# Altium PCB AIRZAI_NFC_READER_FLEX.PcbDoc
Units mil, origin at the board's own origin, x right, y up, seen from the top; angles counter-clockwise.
Board outline 2897.24 x 5858.66 mil, 2 copper layers (Top Layer, Bottom Layer); 43 components, 43 nets, 191 pads, 93 vias.
Unrouted connection lines stored in the file: 129.
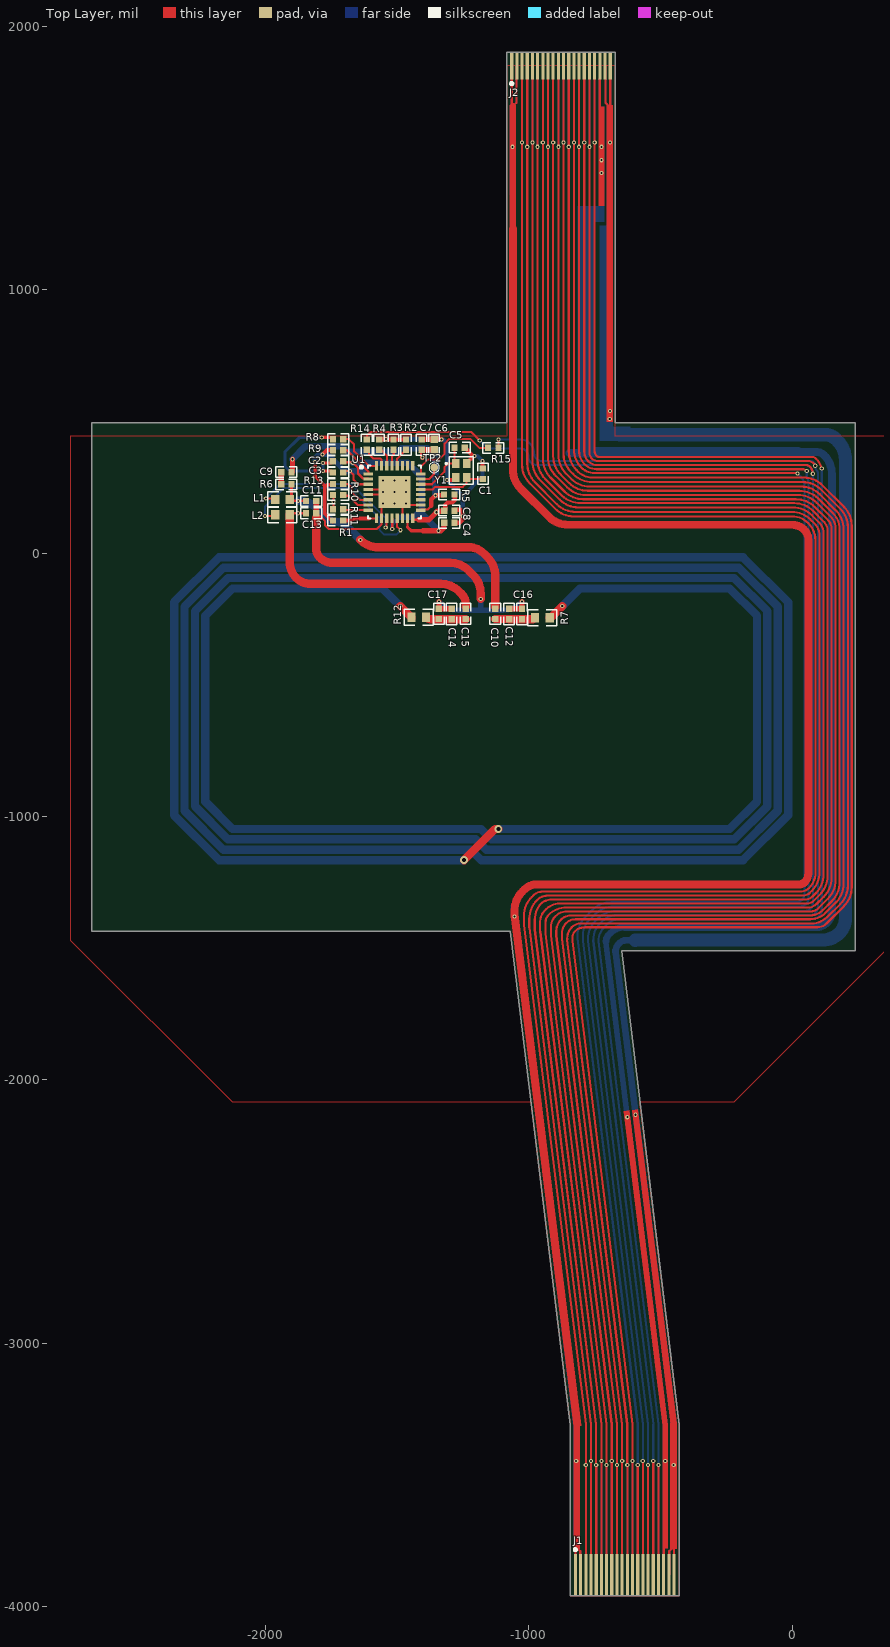
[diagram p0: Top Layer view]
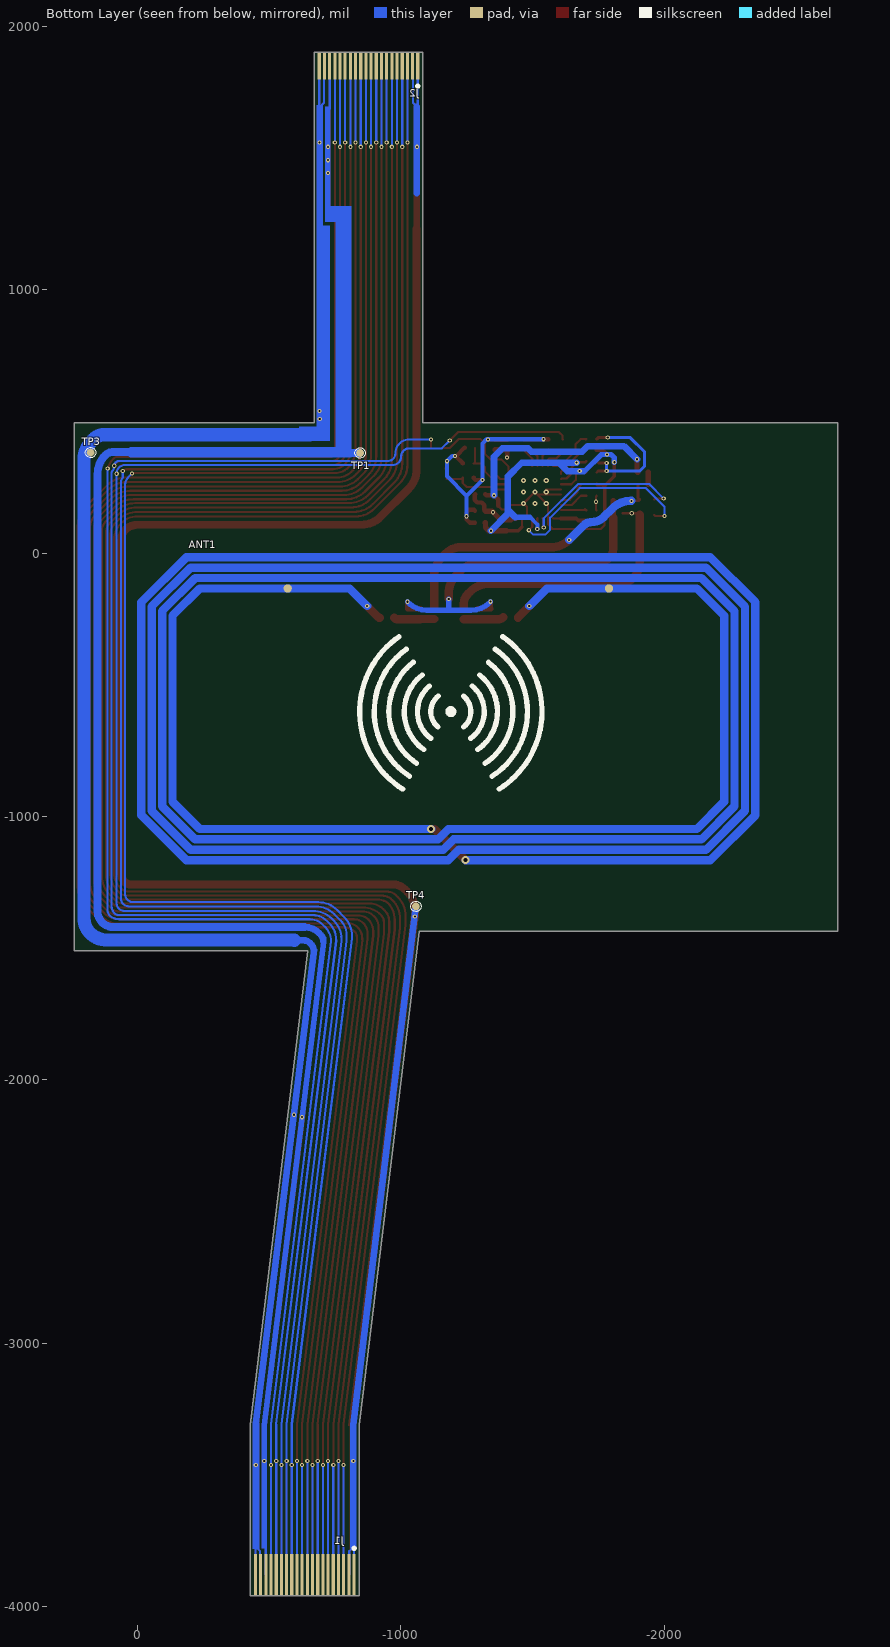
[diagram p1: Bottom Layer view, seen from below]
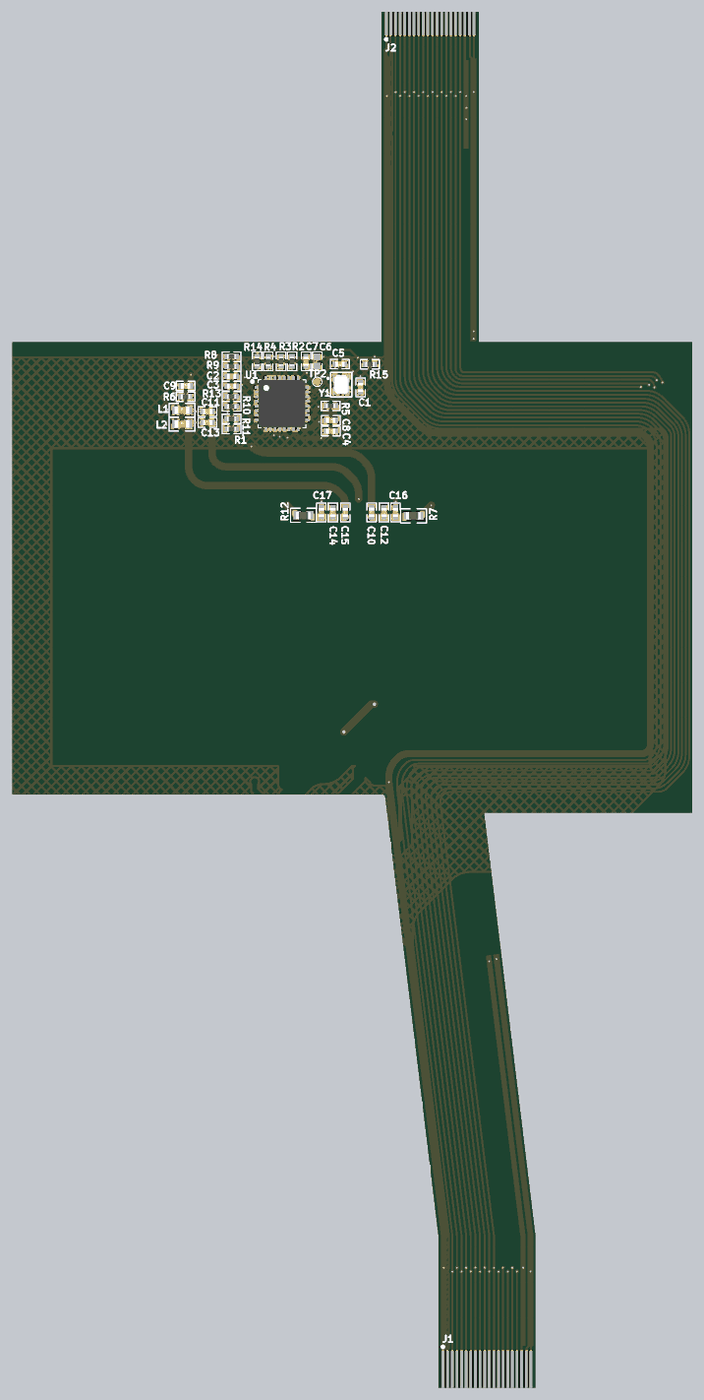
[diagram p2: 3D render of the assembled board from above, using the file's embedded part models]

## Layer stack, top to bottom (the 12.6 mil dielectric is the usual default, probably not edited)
Top Solder: solder mask 0.4, Solder Resist, Dk 3.5
Top Layer: signal copper 1.4
Dielectric 1: dielectric 12.6, FR-4, Dk 4.8
Bottom Layer: signal copper 1.4
Bottom Solder: solder mask 0.4, Solder Resist, Dk 3.5

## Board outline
-2658.83,-1434.65 -2658.83,494.46 -1084.81,494.46 -1084.81,1901.16 -671.43,1901.16 -671.43,494.46 238.42,494.46 238.42,-1510 -648.12,-1510 -648.12,-1510.01 -429.3,-3309.99 -429.3,-3957.5 -842.69,-3957.5 -842.69,-3309.99 -1070.67,-1434.65 -1070.68,-1434.65

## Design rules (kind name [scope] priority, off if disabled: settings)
Clearance Clearance_polygon_5V [OnLayer('Keep-Out Layer') vs (InNet('+5V') AND InPolygon)] p1: gap=10 ignorepadtopadclearanceinfootprint=FALSE
Clearance Clearance_POLYGON_KEEPOUT [(OnLayer('Keep-Out Layer')) vs (InNet('GND') AND InPolygon)] p2: gap=10 ignorepadtopadclearanceinfootprint=FALSE
Clearance [All] p3: gap=6 ignorepadtopadclearanceinfootprint=FALSE
MinimumSolderMaskSliver [All] p1: minsoldermaskwidth=1
PolygonConnect [All] p1: connectstyle=Direct reliefconductorwidth=10 reliefentries=4 polygonreliefangle="90 Angle" airgapwidth=10
RoomDefinition AIRZAI_NFC_READER_FLEX [InComponentClass('AIRZAI_NFC_READER_FLEX')] p1: confinementstyle=ConfineIn formatcopy=TRUE lockcomponents=FALSE outline -17880.56,-16733.69 13049.31,-16733.69 13049.31,5823.5 -17880.56,5823.5
RoutingVias [All] p1: holewidth=28 width=50 viastyle="Through Hole" minholewidth=8 minwidth=16 maxholewidth=28 maxwidth=50
SilkToSilkClearance [All] p1: silktosilkclearance=1
SilkToSolderMaskClearance [IsPad] p1: minsilkscreentomaskgap=2 clearancetoexposedcopper=TRUE
SolderMaskExpansion [All] p1: expansion=4
UnRoutedNet [All] p1: checkbadconnections=TRUE
Width [All] p1: maxlimit=100 minlimit=6 preferedwidth=10
26 further rules are at their usual default settings.

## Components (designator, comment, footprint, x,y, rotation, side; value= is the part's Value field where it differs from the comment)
ANT1 "NFC_ANT" ANTENNA-NFC-60MMX30MM -1181.1,-590.55 r180 bottom locked
C1 "12pF" 0402CAP -1174.8,301.42 r270 top
C2 "0.1µF" 0402CAP -1724.45,348.95 r180 top
C3 "0.1µF" 0402CAP -1724.45,306.27 r180 top
C4 "0.1µF" 0402CAP -1301.78,115.39 r0 top
C5 "12pF" 0402CAP -1262.89,400.56 r180 top
C6 "1uF" CAPC0402(1005)60_M -1359.58,412.18 r270 top
C7 "0.1µF" 0402CAP -1406.8,412.31 r90 top
C8 "0.1µF" 0402CAP -1301.78,161.39 r0 top
C9 "1nF" 0402CAP -1920.38,307.56 r0 top
C10 "18pF" 0402CAP -1127.69,-230.53 r90 top
C11 "220pF" 0402CAP -1826.95,198.56 r180 top
C12 "47pF" 0402CAP -1074.78,-230.87 r270 top
C13 "220pF" 0402CAP -1826.95,151.56 r0 top
C14 "47pF" 0402CAP -1293.1,-230.88 r90 top
C15 "18pF" 0402CAP -1239.99,-230.69 r90 top
C16 "DNP" 0402CAP -1025.76,-230.87 r270 top
C17 "DNP" 0402CAP -1341.78,-230.69 r90 top
J1 "FFC Cable" FFC_PADS_MBD -645.83,-3878.76 r180 top locked
J2 "FFC Cable" FFC_PADS_LID -887.96,1849.98 r180 top locked
L1 "560nH" 0603CAP -1935.38,203.56 r0 top
L2 "560mH" 0603CAP -1935.38,145.56 r0 top
R1 "0R" 0402 -1724.42,124.11 r180 top
R2 "10K" 0402 -1466.8,412.31 r270 top
R3 "10K" 0402 -1513.8,412.31 r270 top
R4 "10K" 0402 -1568.42,412.11 r270 top
R5 "1K" 0402 -1302.26,222.84 r180 top
R6 "2.7K" 0402 -1920.7,261.56 r180 top
R7 "3.3" 0603 -948.78,-245.53 r180 top
R8 "10K" 0402 -1724.42,432.89 r180 top
R9 "10K" 0402 -1724.42,391.11 r180 top
R10 "0R" 0402 -1724.26,221.11 r180 top
R11 "0R" 0402 -1724.42,167.11 r180 top
R12 "3.3" 0603 -1417.78,-243.31 r0 top
R13 "10K" 0402 -1724.42,263.11 r180 top
R14 "0R" 0402 -1615.42,412.37 r90 top
R15 "0R" 0402 -1135,399.88 r0 top
TP1 "WIREPT" TP_0.9MM -846,380.56 r90 bottom
TP2 "WIREPT" TP_0.9MM -1359.42,325.11 r270 top
TP3 "WIREPT" TP_0.9MM 177,382 r90 bottom
TP4 "WIREPT" TP_0.9MM -1058,-1341 r90 bottom
U1 "MFRC52202HN1,115" VFQFN-32-MFRC52202HN1,157 -1509.78,232.11 r0 top
Y1 "27.12MHz" XTAL_2016 -1256.78,313.42 r270 top

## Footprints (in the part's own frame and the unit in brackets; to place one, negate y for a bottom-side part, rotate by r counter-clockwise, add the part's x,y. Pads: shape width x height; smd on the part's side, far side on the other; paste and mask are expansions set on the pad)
0402 [mm] "Chip Resistor, Body 1.1x0.5mm, IPC High Density"
  rect 0.6x0.6 smd: 1(-0.5,0) 2(0.5,0)
  silkscreen extent -1.02,-0.51 1.02,0.51, body extent -0.5,-0.25 0.5,0.25, height 0.27
0402CAP [mm] "Chip Capacitor, Body 1.1x0.5mm, IPC High Density"
  rect 0.6x0.6 smd: 1(-0.5,0) 2(0.5,0)
  silkscreen extent -1.02,-0.51 1.02,0.51, body extent -0.5,-0.3 0.5,0.3, height 0.19
0603 [mm] "Chip Resistor, Body 1.6x0.8mm, IPC High Density"
  rect 0.8x0.9 smd: 1(-0.7,0) 2(0.7,0)
  silkscreen extent -1.4,-0.76 1.4,0.76, body extent -0.8,-0.41 0.8,0.4, height 0.37
0603CAP [mm] "Chip Capacitor, Body 1.6x0.8mm, IPC High Density"
  rect 0.8x0.9 smd: 1(-0.7,0) 2(0.7,0)
  silkscreen extent -1.4,-0.76 1.4,0.76, body extent -0.8,-0.4 0.8,0.4, height 0.29
ANTENNA-NFC-60MMX30MM [mm] "ANTENNA-ID2+10P-01"
  round 0.8 smd paste-0.8: 1(-15.494,11.6) 2(15.494,11.6)
  Top Layer lines w0.8: 15.494,11.6 23.97,11.6 26.6,8.97 26.6,-8.97 23.97,-11.6 0,-11.6 -1,-12.6 -24.404,-12.6 -27.6,-9.404 -27.6,9.404 -24.404,12.6 24.404,12.6 27.6,9.404 27.6,-9.404 24.404,-12.6 0.508,-12.6 -0.492,-13.6 -24.838,-13.6 -28.6,-9.838 -28.6,9.838 -24.838,13.6 24.838,13.6 28.6,9.838 28.6,-9.838 24.838,-13.6 1,-13.6 0,-14.6 -25.272,-14.6 -29.6,-10.272 -29.6,10.272 -25.272,14.6 25.272,14.6 29.6,10.272 29.6,-10.272 25.272,-14.6 1.651,-14.6 ; -1.651,-11.6 -23.97,-11.6 -26.6,-8.97 -26.6,8.97 -23.97,11.6 -15.494,11.6
  Bottom Layer lines w0.8: 1.651,-14.6 -1.349,-11.6 -1.651,-11.6
CAPC0402(1005)60_M [mm] "Chip Capacitor, Body 1.0x0.5mm, Height 0.6mm, IPC Low Density"
  rect 0.72x0.72 smd: 1(-0.5,0) 2(0.5,0)
  silkscreen extent -1.02,-0.51 1.02,0.51, body extent -0.55,-0.3 0.55,0.3, height 0.6
FFC_PADS_LID [mm] "(0.50mm"
  rect 0.3x2.6 smd: 1(4.5,0) 2(4,0) 3(3.5,0) 4(3,0) 5(2.5,0) 6(2,0) 7(1.5,0) 8(1,0) 9(0.5,0) 10(0,0) 11(-0.5,0) 12(-1,0) 13(-1.5,0) 14(-2,0) 15(-2.5,0) 16(-3,0) 17(-3.5,0) 18(-4,0) 19(-4.5,0) 20(-5,0)
  rect 0.3x2.6 smd far side: 1(4.5,0) 2(4,0) 3(3.5,0) 4(3,0) 5(2.5,0) 6(2,0) 7(1.5,0) 8(1,0) 9(0.5,0) 10(0,0) 11(-0.5,0) 12(-1,0) 13(-1.5,0) 14(-2,0) 15(-2.5,0) 16(-3,0) 17(-3.5,0) 18(-4,0) 19(-4.5,0) 20(-5,0)
  silkscreen extent 4.37,1.58 4.62,1.83
FFC_PADS_MBD [mm] "(0.50mm"
  rect 0.3x4 smd: 1(4.5,0) 2(4,0) 3(3.5,0) 4(3,0) 5(2.5,0) 6(2,0) 7(1.5,0) 8(1,0) 9(0.5,0) 10(0,0) 11(-0.5,0) 12(-1,0) 13(-1.5,0) 14(-2,0) 15(-2.5,0) 16(-3,0) 17(-3.5,0) 18(-4,0) 19(-4.5,0) 20(-5,0)
  rect 0.3x4 smd far side: 1(4.5,0) 2(4,0) 3(3.5,0) 4(3,0) 5(2.5,0) 6(2,0) 7(1.5,0) 8(1,0) 9(0.5,0) 10(0,0) 11(-0.5,0) 12(-1,0) 13(-1.5,0) 14(-2,0) 15(-2.5,0) 16(-3,0) 17(-3.5,0) 18(-4,0) 19(-4.5,0) 20(-5,0)
  silkscreen extent 4.39,-2.56 4.64,-2.31
TP_0.9MM [mm] "0.9MM DIA TESTPOINT"
  round 0.75 smd paste-5 mask+0.05: 1(0,0)
  silkscreen extent -0.5,-0.5 0.5,0.5
VFQFN-32-MFRC52202HN1,157 [mm]
  rect 0.9x0.31 smd: 1(-2.529,1.75) 2(-2.529,1.25) 3(-2.529,0.75) 4(-2.529,0.25) 5(-2.529,-0.25) 6(-2.529,-0.75) 7(-2.529,-1.25) 8(-2.529,-1.75) 17(2.529,-1.75) 18(2.529,-1.25) 19(2.529,-0.75) 20(2.529,-0.25) 21(2.529,0.25) 22(2.529,0.75) 23(2.529,1.25) 24(2.529,1.75)
  rect 0.31x0.9 smd: 9(-1.75,-2.529) 10(-1.25,-2.529) 11(-0.75,-2.529) 12(-0.25,-2.529) 13(0.25,-2.529) 14(0.75,-2.529) 15(1.25,-2.529) 16(1.75,-2.529) 25(1.75,2.529) 26(1.25,2.529) 27(0.75,2.529) 28(0.25,2.529) 29(-0.25,2.529) 30(-0.75,2.529) 31(-1.25,2.529) 32(-1.75,2.529)
  rect 3.1x3.1 smd: 33(0,0)
  silkscreen extent -3.32,-2.55 2.55,2.55, body extent -2.55,-2.55 2.55,2.55, height 1
XTAL_2016 [mm] "2.00mm x 1.60mm"
  rect 0.85x0.75 smd: 1(-0.675,-0.525) 2(0.675,-0.525) 3(0.675,0.525) 4(-0.675,0.525)
  silkscreen extent -1.32,-1.47 1.32,1.14, body extent -1,-0.81 1,0.79, height 0.65

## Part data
C1 C5: library part CAP, "CAP CER 12PF 50V C0G/NP0 0402", Case/Package=0402, Case Code (Metric)=1005, Dielectric=C0G, Dielectric Material=Ceramic, Manufacturer=KEMET, Manufacturer Part Number=C0402C120J5GACTU, Max Operating Temperature=125°C, Min Operating Temperature=-55°C, Package Quantity=1, Supplier Part Number 1=399-1013-6-ND, Temperature Coefficient=30ppm/°C, Tolerance=5%, Voltage=50V
C2 C3 C4 C7 C8: library part C0402-100n, "Capacitor, X7R, ±10%", Case-EIA=0402, Case-Metric=1005, Manufacturer=TDK, Manufacturer Part Number=C1005X7R1C104K, Rated Voltage="16 V", Supplier Part Number 1=445-4952-2-ND, Tolerance=±20%
C6: library part CAP, "CAP 1uF 16V ±10% 0402 (1005 Metric) Thickness 0.6mm SMD", Case/Package=0402, Case Code (Metric)=1005, Dielectric=X5R, Manufacturer="Taiyo Yuden", Manufacturer Part Number=EMK105BJ105KV-F, Max Operating Temperature=85°C, Min Operating Temperature=-55°C, Package Quantity=1, Supplier Part Number 1=587-2477-6-ND, Tolerance=10%, Voltage Rating=16V
C9: library part 56p, "CAP CER 1000PF 50V C0G/NP0 0402", Case/Package=0402, Case Code (Metric)=1005, Dielectric=C0G, Manufacturer=Murata, Manufacturer Part Number=GRM1555C1H102FA01D, Max Operating Temperature=125°C, Min Operating Temperature=-55°C, Package Quantity=1, Supplier Part Number 1=490-6189-1-ND, Tolerance=1%, Voltage=50V
C10 C15: library part 56p, "CAP CER 18PF 50V NP0 0402", Case/Package=0402, Case Code (Metric)=1005, Dielectric=C0G, Manufacturer="Kyocera AVX", Manufacturer Part Number=04025U180FAT2A, Max Operating Temperature=125°C, Min Operating Temperature=-55°C, Package Quantity=10000, Supplier Part Number 1=478-10144-1-ND, Tolerance=1%, Voltage Rating=50V
C11 C13: library part 56p, "CAP CER 220PF 50V NPO 0402", Case/Package=0402, Case Code (Metric)=1005, Dielectric=C0G, Manufacturer=Yageo, Manufacturer Part Number=CC0402FRNPO9BN221, Max Operating Temperature=125°C, Min Operating Temperature=-55°C, Supplier Part Number 1=311-3730-1-ND, Tolerance=1%, Voltage Rating=50V
C12 C14: library part 56p, "CAP CER 47PF 50V C0G/NP0 0402", Dielectric=C0G, Manufacturer=Murata, Manufacturer Part Number=GJM1555C1H470FB01D, Supplier Part Number 1=490-16376-1-ND, Tolerance=1%, Voltage Rating (DC)=50V
C16 C17: library part 56p
J1 J2: library part XF2M-2015-1A-R100, "Cable"
L1: library part Inductor, "FIXED IND 560NH 100MA 1.05 OHM", Case/Package=0603, Case Code (Metric)=1608, Current Rating=100mA, DC Resistance (DCR)=1.05R, Manufacturer=TDK, Manufacturer Part Number=MLF1608DR56JTD25, Max DC Current=30mA, Max Operating Temperature=125°C, Min Operating Temperature=-55°C, Package Quantity=4000, Ratings=AEC-Q200, Self Resonant Frequency=170MHz, Supplier Part Number 1=445-16970-1-ND, Test Frequency=25MHz, Tolerance=5%
L2: library part Inductor, "FIXED IND 560NH 100MA 1.05 OHM", Case/Package=0603, Case Code (Metric)=1608, Current Rating=100mA, DC Resistance (DCR)=1.05R, Inductance=560nH, Manufacturer=TDK, Manufacturer Part Number=MLF1608DR56JTD25, Max DC Current=30mA, Max Operating Temperature=125°C, Min Operating Temperature=-55°C, Package Quantity=4000, Ratings=AEC-Q200, Self Resonant Frequency=170MHz, Supplier Part Number 1=445-16970-1-ND, Test Frequency=25MHz, Tolerance=5%
R1 R10 R11 R14 R15: library part R0402-12k, "Resistor, ±1%, 0.063W", Case-EIA=0402, Case-Metric=1005, Manufacturer=Panasonic, Manufacturer Part Number=ERJ-2GE0R00X, Supplier Part Number 1=P0.0JTR-ND, Tolerance=±5%
R2 R3 R4 R8 R9 R13: library part R0402-12k, "Resistor 10K, ±1%, 0.063W", Case/Package=0402, Case Code (Metric)=1005, Manufacturer="Vishay Dale", Manufacturer Part Number=CRCW040210K0JNED, Max Operating Temperature=155°C, Max Power Dissipation=63mW, Min Operating Temperature=-55°C, Package Quantity=1, Resistance=10kR, Supplier Part Number 1=541-10KJDKR-ND, Temperature Coefficient=200ppm/°C, Tolerance=5%, Voltage Rating=50V
R5: library part R0402-12k, "RES SMD 1K OHM 1% 1/16W 0402", Case/Package=0402, Case Code (Metric)=1005, Manufacturer=Yageo, Manufacturer Part Number=RC0402FR-071KL, Max Operating Temperature=155°C, Min Operating Temperature=-55°C, Power Rating=62.5mW, Resistance=1kR, Supplier Part Number 1=311-1.00KLRCT-ND, Temperature Coefficient=100ppm/°C, Tolerance=1%, Voltage Rating=50V
R6: library part R0402-12k, "RES SMD 2.7K OHM 1% 1/16W 0402", Case/Package=0402, Manufacturer="Yageo Phycomp", Manufacturer Part Number=RC0402FR-072K7L, Max Operating Temperature=155°C, Min Operating Temperature=-55°C, Power Rating=63mW, Resistance=2.7kR, Supplier Part Number 1=311-2.70KLRCT-ND, Temperature Coefficient=100ppm/°C, Tolerance=1%, Voltage Rating (DC)=50V
R7 R12: library part R0402-12k, "RES SMD 3.3 OHM 1% 1/10W 0603", Case/Package=0603, Manufacturer=Yageo, Manufacturer Part Number=AC0603FR-073R3L, Max Operating Temperature=155°C, Max Power Dissipation=100mW, Min Operating Temperature=-55°C, Resistance=3.3R, Supplier Part Number 1=YAG5335CT-ND, Temperature Coefficient=200ppm/°C, Tolerance=1%
U1: library part MFRC52201HN1,157, "IC RFID READER 13.56MHZ 32HVQFN", Frequency=13.56MHz, Manufacturer="NXP Semiconductors", Max Operating Temperature=85°C, Min Operating Temperature=-25°C, Package Quantity=1500, Supplier Part Number 1=568-15200-1-ND
Y1: library part ZTB_2, "CRYSTAL 27.12MHZ 10PF SMD", Manufacturer="ECS International", Manufacturer Part Number=ECS-271.2-10-37-CKM-TR, Supplier Part Number 1=XC2511DKR-ND

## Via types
v1: diameter 16, hole 8, Top Layer to Bottom Layer, tented both sides, 82 vias
v2: diameter 19.68, hole 8, Top Layer to Bottom Layer, 9 vias
v3: diameter 30, hole 15, Top Layer to Bottom Layer, tented both sides, 2 vias

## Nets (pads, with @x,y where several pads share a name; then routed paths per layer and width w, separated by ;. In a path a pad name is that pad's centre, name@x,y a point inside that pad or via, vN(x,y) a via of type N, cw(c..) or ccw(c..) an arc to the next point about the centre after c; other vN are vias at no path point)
3V3: C2.1 C3.1 C4.1 C6.2 C7.1 J1.18 J2.18 R1.2 R9.2 R13.2 TP1.1 U1.2 U1.3 U1.12 U1.15 | length 5940.6
  Top Layer w8: C3.1 -1699.47,311.56 v1(-1679.83,311.56) -1665.26,297 -1665.26,278.56 -1648.34,261.64 U1.3 ; C2.1 -1700.95,345.14 -1669.96,345.14 -1648.81,324 -1648.81,302.51 -1629.72,283.42 -1611.45,283.42 U1.2 ; U1.12 -1518.85,131.77 v1(-1518.85,91.33) ; -1460.57,100.87 U1.15
  Top Layer w10: -730.58,1686.72 -730.48,1686.83 J2.18@-730.48,1799.31 ; -488.46,-3766.18 -488.35,-3766.28 J1.18@-488.35,-3878.76
  Top Layer w12: -1460.57,100.87 -1460.57,98.63 -1446.8,84.87 -1401.8,84.87
  Top Layer w13: v1(-1811.42,345.33) -1811.42,292.25 -1774.6,255.42 -1774.6,250.33 ; R1.2@-1743.95,119.08 -1774.6,149.73 -1774.6,250.33 ; R13.2@-1743.95,262.08 -1746.7,259.33 -1765.6,259.33 -1774.6,250.33
  Top Layer w15: v1(-1783.42,374.73) -1767.05,391.11 R9.2
  Top Layer w17: v1(-1404.11,363.11) C7.1@-1404.11,387.93
  Top Layer w20: C7.1@-1404.11,387.93 -1407.8,391.62 C7.1 -1359.7,392.62 C6.2 ; -1401.8,84.87 -1401.41,85.25 v1(-1342.65,85.25) -1334.26,85.25 -1322.26,97.25 -1322.26,114.58 C4.1
  Bottom Layer w10: -730.58,1686.72 -730.48,1686.83 J2.18@-730.48,1799.31 ; -488.46,-3766.18 -488.35,-3766.28 J1.18@-488.35,-3878.76
  Bottom Layer w15: v1(-1518.85,91.33) -1518.85,109.07 -1491.06,136.87
  Bottom Layer w20: v1(-1811.42,345.33) -1811.42,362.11 -1798.8,374.73 v1(-1783.42,374.73) -1762.05,374.73 -1698.88,311.56 -1694.39,311.56 ; -1491.06,136.87 -1434.61,136.87
  Bottom Layer w25: -1694.39,311.56 v1(-1679.83,311.56) -1632.96,311.56 -1600.91,343.61 ; v1(-1668.42,343.61) -1600.91,343.61 ; -1434.61,136.87 -1407.8,163.68 ; v1(-1342.65,85.25) -1407.8,150.4 -1407.8,163.68 ; -707,-1473.46 cw(c-672.1,-1473.46) -696.78,-1448.78 -690,-1442 cw(c-634.47,-1497.53) -634.47,-1419 ; -1600.91,343.61 -1459.93,343.61 -1407.42,291.11 -1407.42,164.05 -1407.8,163.68
  Bottom Layer w30: TP1.1 -792.45,380.56 -789.54,383.47 ; -634.47,-1419 91.96,-1419 ccw(c91.96,-1360.96) 133,-1402 ccw(c91.43,-1360.43) 150.22,-1360.43 150.22,-1080 150.22,301.05 ccw(c50.22,301.05) 120.93,371.76 120.22,372.47 ccw(c93.66,345.92) 93.66,383.47 21,383.47
  Bottom Layer w40: -789.54,383.47 21,383.47
  other v1: -482.26,-3446.18 -626.15,-2141.18 -724.39,1443 -724,1492 -724.39,1542.72
+5: J1.19 J1.20 J2.19 J2.20 TP3.1 | length 4624.8
  Top Layer w8: J2.19@-710.8,1849.98 -709.02,1848.2 -709.02,1709.63 -691.11,1691.72 J2.20@-691.11,1799.31 ; J1.19@-468.67,-3878.76 -466.89,-3876.98 -466.89,-3789.09 -448.98,-3771.18 J1.20@-448.98,-3878.76
  Bottom Layer w8: J2.19@-710.8,1849.98 -709.02,1848.2 -709.02,1709.63 -691.11,1691.72 J2.20@-691.11,1799.31 ; J1.19@-468.67,-3878.76 -466.89,-3876.98 -466.89,-3789.09 -448.98,-3771.18 J1.20@-448.98,-3878.76
  Bottom Layer w25: -671,-1513 cw(c-627.54,-1513) -658.27,-1482.27 -656,-1480 cw(c-631.86,-1504.14) -631.86,-1470 -601,-1469
  Bottom Layer w40: -687.58,461.82 ccw(c-656.2,493.2) -656.2,448.82
  Bottom Layer w50: -656.2,449.82 125.76,449.82 cw(c125.76,394.01) 165.22,433.47 172.25,426.44 cw(c101.54,355.73) 201.54,355.73 201.54,-1080 201.54,-1387.58 cw(c124.58,-1387.58) 179,-1442 cw(c113.85,-1376.85) 113.85,-1468.98 -595.78,-1468.98 -596,-1469.2
  other v1: -450.26,-3462.18 -595,-2132 -693,509 -692.39,540 -692.39,1558.72
ACCELERO_INT: J1.14 J2.14 | length 8005.1
  Top Layer w8: J2.14@-809.22,1799.31 -809.22,387.95 ccw(c-738.33,387.95) -788.46,337.82 ccw(c-742.59,383.69) -742.59,318.82 38.54,318.82 cw(c38.54,295.54) v1(55,312) ; J1.14@-567.09,-3878.76 v1@-567.09,-3446.18
  Bottom Layer w8: v1@-809.22,1542.72 J2.14@-809.22,1799.31 ; -794.83,-1471 -794.83,-1470.35 ; J1.14@-567.09,-3878.76 -567.09,-3308.35 ; -566.9,-3308.35 -794.75,-1470.99 -794.83,-1470.35 ; v1(55,312) 55,287.83 ccw(c61.83,287.83) 57,283 cw(c47.34,273.34) 61,273.34 61,-1315.51 cw(c40.51,-1315.51) 55,-1330 cw(c28.44,-1303.44) 28.44,-1341 -677.58,-1341 ccw(c-677.58,-1441) -748.29,-1370.29 -773,-1395 ccw(c-720.29,-1447.71) -794.83,-1447.71 -794.83,-1470.35
  other v1: -567.46,-3446.18 -809.58,1542.72
ADC_CH1: J1.5 J2.5 | length 8347.6
  Top Layer w8: J2.5@-986.39,1799.31 -986.39,348.17 ccw(c-886.39,348.17) -957.1,277.46 -882.75,203.11 ccw(c-812.04,273.82) -812.04,173.82 3.15,173.82 cw(c3.15,73.82) 73.86,144.53 103,115.39 cw(c64.37,76.76) 119,76.76 119,-1219.99 cw(c19.99,-1219.99) 90,-1290 76.75,-1303.25 cw(c48.38,-1274.87) 48.38,-1315 -911.72,-1315 ccw(c-911.72,-1383.28) -950.59,-1327.15 ccw(c-885.19,-1392.55) -977.68,-1392.55 -977.68,-1427.7 -744.46,-3308.35 v1(-744.46,-3462.18) ; J1.5@-744.26,-3878.76 v1@-744.26,-3462.18
  Bottom Layer w8: v1@-986.39,1559 J2.5@-986.39,1799.31 ; J1.5@-744.26,-3878.76 v1@-744.26,-3462.18
  other v1: -986.58,1558.72
CAP1_TOUCH_OUT: J1.7 J2.7 | length 8320.1
  Top Layer w8: J2.7@-947.02,1799.31 -947.02,357.8 ccw(c-847.02,357.8) -917.73,287.09 -864.75,234.11 ccw(c-794.04,304.82) -794.04,204.82 14.76,204.82 cw(c14.76,104.82) 85.47,175.53 136,125 cw(c104.62,93.62) 149,93.62 149,-1233.58 cw(c49,-1233.58) 119.71,-1304.29 92,-1332 cw(c60.62,-1300.62) 60.62,-1345 -857.4,-1345 ccw(c-857.4,-1440.6) -925,-1373 ccw(c-897.28,-1400.72) -936.48,-1400.72 -936.48,-1442.43 -705.09,-3308.35 v1@-705.09,-3462.18 ; J1.7@-704.89,-3878.76 v1(-704.89,-3462.18)
  Bottom Layer w8: v1@-947.02,1559 J2.7@-947.02,1799.31 ; J1.7@-704.89,-3878.76 v1(-704.89,-3462.18)
  other v1: -947.02,1558.72
CAP2_TOUCH_OUT: J1.8 J2.8 | length 8342.9
  Top Layer w8: J2.8@-927.33,1799.31 -927.33,364.11 ccw(c-827.33,364.11) -898.04,293.4 -854.75,250.11 ccw(c-784.04,320.82) -784.04,220.82 21.76,220.82 cw(c21.76,120.82) 92.47,191.53 146.33,137.67 cw(c103.64,95) 164,95 164,-1241.58 cw(c64,-1241.58) 134.71,-1312.29 99,-1348 cw(c70.03,-1319.03) 70.03,-1360 -854.74,-1360 ccw(c-854.74,-1422.6) -899,-1378.33 ccw(c-858.35,-1418.98) -915.84,-1418.98 -915.84,-1448.61 ; -915.84,-1450.02 -915.84,-1448.61 ; J1.8@-685.2,-3878.76 v1(-685.2,-3446.18) -685.2,-3308.35 -915.66,-1450 -915.84,-1448.61
  Bottom Layer w8: v1(-927.33,1542.72) J2.8@-927.33,1799.31 ; J1.8@-685.2,-3878.76 v1(-685.2,-3446.18)
EN: J1.17 J2.17 | length 7978.6
  Top Layer w8: J2.17@-750.17,1799.31 -750.17,387.43 ccw(c-723.85,387.43) -742.47,368.83 ccw(c-735.21,376.06) -735.21,365.82 72.12,365.82 cw(c72.12,339.12) 91,358 cw(c33.06,300.06) v1@112.08,321.75 ; J1.17@-508.04,-3878.76 v1(-508.04,-3462.18)
  Bottom Layer w8: v1@-750.17,1559 J2.17@-750.17,1799.31 ; -736,-1472.26 cw(c-662.95,-1472.26) -714.6,-1420.6 -703,-1409 cw(c-656.43,-1455.57) -656.43,-1389.71 69.49,-1389.71 ccw(c69.49,-1339.49) 105,-1375 ccw(c87.91,-1357.91) 112.08,-1357.91 v1(112.08,322) ; -735.74,-1472.23 -508.04,-3308.35 J1.17@-508.04,-3878.76
  other v1: -750.17,1558.72
GND: C1.1 C2.2 C3.2 C4.2 C5.1 C6.1 C7.2 C8.2 C11.1 C12.1 C13.2 C14.2 C16.1 C17.2 J1.1 J1.2 J2.1 J2.2 R2.1 R3.1 R4.1 R8.2 R10.2 R11.2 TP4.1 U1.4 U1.5 U1.10 U1.14 U1.18 U1.33 Y1.2 Y1.4 | length 13272.3
  Top Layer w8: C13.2 -1803.56,151.56 -1774.6,122.6 -1774.6,107.06 -1759.54,92 -1576.9,92 -1558.99,109.9 U1.10 -1558.99,182.9 v2(-1553.09,188.8) U1.33@-1519.62,222.27 ; C2.2@-1750.66,342.42 C2.2 ; C3.2@-1749.43,311.56 C3.2 ; R10.2@-1744.14,218.08 cw(c-1750.27,211.95) -1741.6,211.95 v1(-1741.6,195.11) -1741.6,164.43 R11.2@-1743.95,162.08 ; U1.5 U1.33@-1519.62,222.27 ; U1.4 U1.33@-1553.09,241.95 ; U1.14 -1480.25,175.08 -1466.54,188.8 v2(-1466.47,188.8) ; U1.18 -1460.57,182.9 v2(-1466.47,188.8) ; -1065.13,1691.72 J2.1@-1065.13,1799.31 ; -1060.7,1696.15 -1047.22,1709.63 J2.2@-1047.22,1848.2 ; J1.1@-823,-3878.76 -823,-3771.18 ; -818.57,-3775.61 -805.09,-3789.09 J1.2@-805.09,-3876.98 ; U1.33@-1519.62,222.27 v2(-1509.78,232.11) v2(-1466.47,188.8)
  Top Layer w12: v1(-1786.36,438.92) -1750.14,438.92 R8.2 ; v1@-1776.26,311.56 C3.2@-1749.43,311.56 ; v1@-1776.26,342.42 C2.2@-1750.66,342.42
  Top Layer w16: v1(-1542.07,432.89) -1560.65,432.89 -1561.55,431.99 R3.1 R2.1 ; v1(-1310.6,277.33) -1309.81,278.12 -1284.23,278.12 -1277.46,284.88 Y1.2 ; C4.2 -1263.55,115.39 -1250.6,128.34 v1(-1250.6,140.33) -1250.6,155.32 -1259.97,164.7 -1278.78,164.7 C8.2 ; C5.1 v1@-1212.06,369.42 ; Y1.4 -1236.09,341.97 v1@-1208.64,369.42 ; v1(-1175.6,349.33) -1175.6,321.91 C1.1
  Top Layer w18: C7.2 -1406.74,431.93 -1359.64,431.93 C6.1 -1358.36,430.65 -1356.9,432.11 v1(-1332,432.11)
  Top Layer w20: C13.2 C11.1 ; v1(-1341.51,-184) -1341.51,-210.73 C17.2 -1341.68,-211.1 -1293.19,-211.1 C14.2 ; C12.1 C16.1 v1(-1025.76,-184.46)
  Top Layer w25: -1060.7,1231.72 -1060.7,1696.15 ; -818.57,-3775.61 -818.57,-3311.18
  Top Layer w30: -1060.7,1231.72 -1060.7,316.48 ccw(c-960.7,316.48) -1031.41,245.77 -922.75,137.11 ccw(c-852.04,207.82) -852.04,107.82 -0.43,107.82 cw(c-0.43,43.57) 45,89 cw(c6.37,50.37) 61,50.37 61,-1216.62 cw(c16.62,-1216.62) 48.06,-1247.94 cw(c23.86,-1223.86) 23.86,-1258 -972.54,-1258 ccw(c-972.54,-1319.46) -1016,-1276 -1024.71,-1284.71 ccw(c-954,-1355.42) -1054,-1355.42 v1(-1054,-1379)
  Top Layer w31.5: -1807.26,134.47 -1807.26,16.03 ccw(c-1761.22,16.03) -1793.78,-16.53 ccw(c-1745.5,31.76) -1745.5,-36.53 -1299.2,-36.53 cw(c-1299.2,-136.53) -1228.49,-65.82 -1212.07,-82.24 cw(c-1282.78,-152.95) -1182.78,-152.95 v1(-1182.78,-173.53)
  Bottom Layer w8: -1065.13,1691.72 J2.1@-1065.13,1799.31 ; -1061.58,1695.27 -1047.22,1709.63 J2.2@-1047.22,1848.2 ; J1.1@-823,-3878.76 -823,-3771.18 ; -819.46,-3774.72 -805.09,-3789.09 J1.2@-805.09,-3876.98
  Bottom Layer w12: v1(-1786.36,438.92) -1871.61,438.92 -1926.42,384.11 -1926.42,331.11 -1906.88,311.56 v1(-1782.26,311.56) v1(-1782.26,342.42)
  Bottom Layer w16: v1(-1542.07,432.89) -1326.98,432.89 -1310.6,416.51 v1(-1310.6,277.33) -1250.6,217.33 ; v1(-1250.6,140.33) -1250.6,217.33 ; v1(-1206.78,369.42) -1195.7,369.42 v1(-1175.6,349.33) -1175.6,292.33 -1250.6,217.33
  Bottom Layer w20: v1(-1341.51,-184) -1338.27,-187.24 ccw(c-1267.56,-116.53) -1267.56,-216.53 -1182.78,-216.53 ; v1(-1182.78,-173.53) -1182.78,-216.53 ; v1(-1025.76,-184.46) -1028.54,-187.24 cw(c-1099.25,-116.53) -1099.25,-216.53 -1182.78,-216.53
  Bottom Layer w25: -1061.58,1366.72 -1061.58,1695.27 ; TP4.1@-1058.14,-1341.02 -819.46,-3311.18 -819.46,-3774.72
  other v1: -820.46,-3446.18 -1062.58,1542.72
  other v2: -1509.78,188.8 -1553.09,232.11 -1466.47,232.11 -1553.09,275.42 -1509.78,275.42 -1466.47,275.42
"LED Str CLK": J1.10 J2.10 | length 8316
  Top Layer w8: J2.10@-887.96,1799.31 -887.96,372.74 ccw(c-787.96,372.74) -858.67,302.03 -837.46,280.82 ccw(c-769.86,348.42) -769.86,252.82 33.76,252.82 cw(c33.76,152.82) 104.47,223.53 165.71,162.29 cw(c95,91.58) 195,91.58 195,-1255.58 cw(c95,-1255.58) 165.71,-1326.29 125.83,-1366.17 cw(c69,-1309.34) 69,-1389.71 -823.5,-1389.71 ccw(c-823.5,-1438.5) -858,-1404 ccw(c-817.87,-1444.13) -874.62,-1444.13 -874.62,-1462.9 ; -874.69,-1462.96 -645.83,-3308.35 v1(-645.83,-3446.18) J1.10@-645.83,-3878.76
  Bottom Layer w8: v1(-887.96,1542.72) J2.10@-887.96,1799.31 ; J1.10@-645.83,-3878.76 v1(-645.83,-3446.18)
"LED Str DATA": J1.11 J2.11 | length 8270
  Top Layer w8: J2.11@-868.28,1799.31 -868.28,375.98 ccw(c-773.3,375.98) -840.46,308.82 -830.75,299.11 ccw(c-760.04,369.82) -760.04,269.82 39.66,269.82 cw(c39.66,169.82) 110.37,240.53 181.71,169.18 cw(c111,98.47) 211,98.47 211,-1261.58 cw(c111,-1261.58) 181.71,-1332.29 133,-1381 cw(c72.64,-1320.64) 72.64,-1406 -803.2,-1406 ccw(c-803.2,-1453.8) -837,-1420 ccw(c-794.82,-1462.18) -854.47,-1462.18 -854.47,-1466.73 ; -854.7,-1466.96 -626.35,-3308.35 v1@-626.35,-3462.18 ; J1.11@-626.15,-3878.76 v1(-626.15,-3462.18)
  Bottom Layer w8: v1@-868.28,1559 J2.11@-868.28,1799.31 ; J1.11@-626.15,-3878.76 v1(-626.15,-3462.18)
  other v1: -868.28,1558.72
NetANT1_1: ANT1.1 R7.1 | length 407.1
  Top Layer w31.5: R7.1 ccw(c-921.22,-238.6) -916.32,-243.5 v1(-873.12,-200.29)
  Bottom Layer w31.5: -1802.1,-133.87 -1791.1,-133.87 ; v1(-873.12,-200.29) -806.7,-133.87 ANT1.1
NetANT1_2: ANT1.2 R12.1 | length 391
  Top Layer w31.5: v1@-1488.45,-200.2 R12.1
  Bottom Layer w31.5: ANT1.2 -1554.97,-133.87 v1(-1488.55,-200.29)
NetC1_2: C1.2 U1.21 Y1.3 | length 268.4
  Top Layer w8: U1.21 -1364.83,241.95 -1355.13,251.65 -1250.34,251.65 -1236.09,265.9 Y1.3 -1230.98,281.74 C1.2
NetC5_2: C5.2 U1.22 Y1.1 | length 236.2
  Top Layer w8: U1.22 -1368.11,261.64 -1320.8,308.94 -1320.8,325.87 -1306.8,339.87 -1277.6,339.87 Y1.1 -1282.8,345.33 C5.2@-1282.8,398.87
NetC9_1: C9.1 R6.2 | length 46.1
  Top Layer w20: R6.2 -1940.07,261.88 C9.1
NetC9_2: C9.2 R5.2 U1.17 | length 914.3
  Top Layer w8: U1.17 -1408.11,165.31 -1385.05,165.31 -1369.8,180.56
  Top Layer w17: -1369.8,180.56 -1369.8,204.17 v1(-1354.45,219.53) -1325.26,219.53 R5.2
  Top Layer w20: C9.2 C9.2@-1898.88,309.37 ; C9.2@-1897.61,309.37 v1(-1897.61,356.43)
  Bottom Layer w25: v1(-1897.61,356.43) -1847.66,406.39 -1710.42,406.39 -1689.14,385.11 -1496.71,385.11 -1483.71,398.11 -1386.42,398.11 -1354.45,366.13 v1(-1354.45,219.53)
NetC10_1: C10.1 C12.2 C16.2 R7.2 | length 152.8
  Top Layer w31.5: C10.1 -1075.13,-250.21 C12.2 C16.2 -988.48,-250.56 ccw(c-988.48,-233.38) R7.2
NetC10_2: C10.2 C11.2 L1.2 R6.1 | length 1115.4
  Top Layer w10: R6.1 -1901.01,210.37 L1.2 -1902.82,198.56 v1(-1876.23,198.56) C11.2 C11.2@-1843.64,198.56
  Top Layer w31.5: v1(-1639.85,50.47) ccw(c-1572.25,118.07) -1572.25,22.47 -1228.72,22.47 cw(c-1228.72,-59.47) -1170.78,-1.53 -1156.98,-15.33 cw(c-1227.69,-86.04) -1127.69,-86.04 -1127.69,-172.53 C10.2@-1127.68,-204.53
  Bottom Layer w31.5: v1(-1876.23,198.56) -1874.29,198.56 cw(c-1874.29,98.56) -1803.58,169.27 -1771.16,136.86 ccw(c-1726.78,181.24) -1726.78,118.47 cw(c-1726.78,72.77) -1694.47,105.1 v1(-1639.85,50.47)
NetC13_1: C13.1 C15.2 L2.2 | length 1011.1
  Top Layer w10: L2.2 -1901.82,151.56 v1(-1877.6,151.56) C13.1 C13.1@-1843.63,151.56
  Top Layer w31.5: L2.2 -1907.82,-34.03 ccw(c-1822.32,-34.03) -1882.78,-94.49 ccw(c-1829.57,-41.28) -1829.57,-116.53 -1335.2,-116.53 cw(c-1335.2,-216.53) -1264.49,-145.82 -1254.78,-155.53 cw(c-1290.48,-191.23) -1239.99,-191.23 C15.2@-1239.99,-203.53
NetC14_1: C14.1 C15.1 C17.1 R12.2 | length 154.2
  Top Layer w31.5: -1445.36,-245.84 -1445.36,-243.87 ; R12.2 ccw(c-1373.17,-226.26) -1373.17,-250.37 C17.1 -1341.59,-250.56 C14.1 -1292.9,-250.37 C15.1
NetL1_1: L1.1 U1.11 | length 643.2
  Top Layer w8: v1(-1998.6,207.33) -1966.7,207.33 L1.1 ; v1(-1543.6,97.33) -1541.21,97.33 -1542.07,98.19 -1542.07,101.02 -1540.27,102.82 -1540.27,131.58 U1.11
  Bottom Layer w8: v1(-1998.6,207.33) -1943.28,262.65 -1673.92,262.65 -1543.6,132.33 v1(-1543.6,97.33)
NetL2_1: L2.1 U1.13 | length 776.8
  Top Layer w8: v1(-2001.6,141.33) -1967.18,141.33 L2.1 ; U1.13 -1499.94,100.46 v1(-1486.8,87.33)
  Bottom Layer w8: v1(-2001.6,141.33) -2001.6,176.88 -1931.5,246.98 -1680.25,246.98 -1567.6,134.33 -1567.6,89.33 -1548.92,70.65 -1503.48,70.65 v1(-1486.8,87.33)
NetR1_1: R1.1 U1.9 | length 124.2
  Top Layer w8: -1608.26,131.71 -1579.14,132.08 U1.9
  Top Layer w15: R1.1@-1699.46,124.15 -1674.83,124.06 -1666.9,131.93 -1608.26,131.71
NetR2_2: R2.2 U1.28 | length 74.9
  Top Layer w8: U1.28 -1499.94,358.83 -1466.47,392.29 R2.2
NetR3_2: R3.2 U1.29 | length 64.2
  Top Layer w8: U1.29 -1519.62,367.91 -1512.8,374.73 -1512.8,391.62 R3.2
NetR4_2: R4.2 U1.30 | length 70.2
  Top Layer w8: R4.2@-1561.55,392.62 -1539.31,370.38 U1.30
NetR8_1: R8.1 U1.32 | length 193.9
  Top Layer w8: R8.1@-1702.88,431.03 R8.1 ; R8.1@-1696.73,432.89 R8.1 ; U1.32 -1608.54,331.67 -1663.42,386.56 -1663.42,412.71 -1683.61,432.89 R8.1
NetR9_1: R9.1 U1.1 | length 138
  Top Layer w8: R9.1 -1690.42,391.11 -1609.35,310.03 U1.1
NetR10_1: R10.1 U1.7 | length 110
  Top Layer w8: R10.1@-1704.77,218.08 -1684.39,218.08 -1649.21,182.9 U1.7
NetR11_1: R11.1 U1.8 | length 102.7
  Top Layer w8: R11.1@-1704.58,162.08 R11.1@-1699.28,167.37 ; R11.1@-1704.58,163.21 U1.8
NetR13_1: R13.1 U1.6 | length 129.2
  Top Layer w8: R13.1@-1704.58,262.08 -1686.78,262.08 -1672.26,247.56 -1672.26,231.95 -1642.74,202.42 -1609.5,202.42 U1.6
NetR14_1: R14.1 U1.31 | length 97.5
  Top Layer w8: R14.1@-1608.22,392.74 -1606.8,391.31 -1606.8,375.17 -1591.74,360.11 -1564.42,360.11 -1558.99,354.68 U1.31
NetR15_1: R15.1 U1.24 | length 363.2
  Top Layer w8: U1.24 -1410.21,327.84 -1382.05,356 -1341.26,356 -1320,377.26 -1320,416 -1302.01,433.99 -1221.85,433.99 -1187.74,399.88 R15.1
NetTP2_1: TP2.1 U1.23 | length 94.4
  Top Layer w8: U1.23 -1379.01,281.32 -1359.8,300.53 TP2.1@-1359.8,336.56
NFC_INT: J1.12 J2.12 | length 8294.1
  Top Layer w8: J2.12@-848.59,1799.31 -848.59,386.37 ccw(c-748.59,386.37) -819.3,315.66 -812.46,308.82 ccw(c-759.34,361.93) -759.34,286.82 44,286.82 cw(c44,187.19) 114.45,257.64 196.71,175.37 cw(c126,104.66) 226,104.66 226,-1268.58 cw(c126,-1268.58) 196.71,-1339.29 130,-1406 cw(c96.2,-1372.2) 96.2,-1420 -786.37,-1420 ccw(c-786.37,-1474.63) -825,-1436 ccw(c-803.27,-1457.73) -834,-1457.73 -834,-1471 ; -834.31,-1471.04 -606.46,-3308.35 v1(-606.46,-3446.18) J1.12@-606.46,-3878.76
  Bottom Layer w8: v1(-848.59,1542.72) J2.12@-848.59,1799.31 ; J1.12@-606.46,-3878.76 v1(-606.46,-3446.18)
PWM1: J1.4 J2.4 | length 8392.6
  Top Layer w8: J2.4@-1006.07,1799.31 -1006.07,339.85 ccw(c-906.07,339.85) -976.78,269.14 -893.75,186.11 ccw(c-823.04,256.82) -823.04,156.82 -1.24,156.82 cw(c-1.24,56.82) 69.47,127.53 84,113 cw(c35.72,64.72) 104,64.72 104,-1210.58 cw(c4,-1210.58) 74.71,-1281.29 67,-1289 cw(c40.44,-1262.44) 40.44,-1300 -927.96,-1300 ccw(c-927.96,-1358.04) -969,-1317 -969.06,-1317.06 ccw(c-898.35,-1387.77) -998.35,-1387.77 -998.35,-1418.17 ; -998.35,-1420.81 -998.35,-1418.17 ; J1.4@-763.94,-3878.76 v1(-763.94,-3446.18) -763.94,-3308.35 -998.03,-1420.77 -998.35,-1418.17
  Bottom Layer w8: v1(-1006.07,1542.72) J2.4@-1006.07,1799.31 ; J1.4@-763.94,-3878.76 v1(-763.94,-3446.18)
PWM2: J1.3 J2.3 | length 8368.7
  Top Layer w8: J2.3@-1025.76,1799.31 -1025.76,335.84 ccw(c-925.76,335.84) -996.47,265.13 -900.44,169.11 ccw(c-829.73,239.82) -829.73,139.82 -1.33,139.82 cw(c-1.33,51.67) 61,114 cw(c-4.18,48.82) 88,48.82 88,-1213.06 cw(c6.06,-1213.06) 64,-1271 cw(c30.2,-1237.2) 30.2,-1285 -947.79,-1285 ccw(c-947.79,-1336.21) -983.99,-1299.99 -989.61,-1305.61 ccw(c-918.9,-1376.32) -1018.9,-1376.32 -1018.9,-1411.24 -783.63,-3308.35 v1(-783.63,-3462.18) J1.3@-783.63,-3878.76
  Bottom Layer w8: v1@-1025.76,1559 J2.3@-1025.76,1799.31 ; J1.3@-783.63,-3878.76 v1(-783.63,-3462.18)
  other v1: -1025.76,1558.72
SCL: J1.15 J2.15 R14.2 | length 9821.7
  Top Layer w8: R14.2 -1615,432.48 -1615,446 -1601,460 -1218.61,460 v1(-1186.61,428) ; -789.58,1382.77 -789.58,385.34 ccw(c-737.94,385.34) -774.46,348.82 ccw(c-740.66,382.62) -740.66,334.82 50.54,334.82 cw(c50.54,311.54) 67,328 cw(c40.44,301.44) v1(78,301.44) ; -789.54,1382.77 J2.15@-789.54,1799.31 ; J1.15@-547.41,-3878.76 -547.41,-3479.23 -547.46,-3479.18 v1(-547.46,-3462.23) v1@-547.41,-3462.18
  Bottom Layer w8: v1(-1186.61,428) -1156.61,398 -1033,398 cw(c-1033,367) -1002,367 ccw(c-969.82,367) -969.82,334.82 47,334.82 cw(c47,303.82) 78,303.82 v1(78,301.44) 78,-1328.62 cw(c47.62,-1328.62) 69.1,-1350.1 cw(c50.03,-1331.03) 50.03,-1358 -659.83,-1358 -659.92,-1357.91 -667.49,-1357.91 ccw(c-667.49,-1457.91) -738.2,-1387.2 -747,-1396 ccw(c-678.76,-1464.24) -775.26,-1464.24 -775.26,-1471 -547.41,-3308.35 ; v1(-789.58,1558.77) J2.15@-789.54,1849.98 ; -547.46,-3308.35 -547.46,-3479.18 -547.41,-3479.23 J1.15@-547.41,-3878.76
SDA: J1.16 J2.16 R15.2 | length 9321.8
  Top Layer w8: R15.2 v1(-1115.31,432.11) ; J2.16@-769.85,1799.31 -769.85,380.08 ccw(c-741.19,380.08) -761.46,359.82 ccw(c-737.31,383.96) -737.31,349.82 61.12,349.82 cw(c61.12,323.12) 80,342 cw(c38.96,300.96) v1@87.25,333.16 ; J1.16@-527.72,-3878.76 v1(-527.72,-3446.18) -527.72,-3462.18
  Bottom Layer w8: v1(-1115.31,432.11) -1034.11,432.11 cw(c-1034.11,378) -980,378 ccw(c-951.82,378) -951.82,349.82 69.43,349.82 cw(c69.43,332) v1(87.25,332) 87.25,330.28 ccw(c113.72,330.28) 95,311.56 cw(c90.17,306.73) 97,306.73 97,-1340.44 cw(c59.44,-1340.44) 86,-1367 cw(c69.1,-1350.1) 69.1,-1374 -665.47,-1374 ccw(c-665.47,-1452.53) -721,-1397 -728.72,-1404.72 ccw(c-664.8,-1468.63) -755.19,-1468.63 ; v1(-769.85,1542.72) J2.16@-769.85,1799.31 ; -755.62,-1469.06 -527.53,-3308.35 ; J1.16@-527.72,-3878.76 -527.72,-3308.35
SPR_GPO1: J1.9 J2.9 | length 8297.4
  Top Layer w8: J2.9@-907.65,1799.31 -907.65,368.1 ccw(c-807.65,368.1) -878.36,297.39 -847.07,266.11 ccw(c-776.36,336.82) -776.36,236.82 27.76,236.82 cw(c27.76,136.82) 98.47,207.53 155.25,150.75 cw(c95.5,91) 180,91 180,-1249.58 cw(c80,-1249.58) 150.71,-1320.29 116,-1355 cw(c67.72,-1306.72) 67.72,-1375 -839.37,-1375 ccw(c-839.37,-1429.63) -878,-1391 ccw(c-834.13,-1434.87) -896.17,-1434.87 -896.17,-1450.02 -665.72,-3308.35 v1@-665.72,-3462.18 ; J1.9@-665.52,-3878.76 v1(-665.52,-3462.18)
  Bottom Layer w8: v1@-907.65,1559 J2.9@-907.65,1799.31 ; J1.9@-665.52,-3878.76 v1(-665.52,-3462.18)
  other v1: -907.65,1558.72
SPR_GPO2: J1.6 J2.6 | length 8363.8
  Top Layer w8: J2.6@-966.7,1799.31 -966.7,352.48 ccw(c-866.7,352.48) -937.41,281.77 -874.75,219.11 ccw(c-804.04,289.82) -804.04,189.82 7.98,189.82 cw(c7.98,89.82) 78.69,160.53 120.22,119 cw(c86.95,85.73) 134,85.73 134,-1225.58 cw(c34,-1225.58) 104.71,-1296.29 81,-1320 cw(c56.86,-1295.86) 56.86,-1330 -883.3,-1330 ccw(c-883.3,-1401.7) -934,-1351 -940.03,-1357.03 ccw(c-899.06,-1398) -957,-1398 -957,-1435.53 -956.8,-1435.73 -724.57,-3308.35 v1(-724.57,-3446.18) J1.6@-724.57,-3878.76
  Bottom Layer w8: v1(-966.7,1542.72) J2.6@-966.7,1799.31 ; J1.6@-724.57,-3878.76 v1(-724.57,-3446.18)
TOFINT: J1.13 J2.13 | length 7959.4
  Top Layer w8: J2.13@-828.91,1799.31 -828.91,393.5 ccw(c-731.78,393.5) -800.46,324.82 ccw(c-749.76,375.52) -749.76,303.82 v1@20.48,303.82 ; J1.13@-586.78,-3878.76 v1(-586.78,-3462.18)
  Bottom Layer w8: v1@-828.91,1559 J2.13@-828.91,1799.31 ; J1.13@-586.78,-3878.76 -586.78,-3308.35 -815.88,-1460.94 -815.88,-1453.3 cw(c-715.88,-1453.3) -786.59,-1382.59 -758.29,-1354.29 cw(c-687.58,-1425) -687.58,-1325 15.27,-1325 ccw(c15.27,-1294.27) 37,-1316 ccw(c15.27,-1294.27) 46,-1294.27 46,258 ccw(c0.13,258) 32.56,290.44 v1(20,303)
  other v1: -828.91,1558.72
VMID: C8.1 R5.1 U1.16 | length 227.7
  Top Layer w8: U1.16 -1440.88,128.97 -1438.78,126.87 -1418.8,126.87
  Top Layer w17: C8.1 -1318.15,164.7 -1318.15,182.47 -1308.19,192.43 -1290.61,192.43 -1280.61,202.43 -1280.61,220.87 R5.1
  Top Layer w20: -1418.8,126.87 -1379.65,126.87 v1(-1351.26,155.25) -1346.95,159.57 -1323.28,159.57 C8.1
pads on no net: U1.19 U1.20 U1.25 U1.26 U1.27
copper on no net:
  other v3: -1246.1,-1165.35 -1116.1,-1047.24

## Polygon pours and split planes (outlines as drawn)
GND on Top Layer "GND TOP" (hatched 45Degree grid 30 track 9.5, remove dead copper, shelved, pour order 1): -2126.78,-2082.53 -991.91,-2082.53 -842.69,-3309.99 -842.69,-3957.5 -429.3,-3957.5 -429.3,-3309.99 -578.52,-2082.53 -220.01,-2082.53 393.54,-1468.98 393.54,443.8 -671.43,443.8 -671.43,1850.49 -1084.81,1850.49 -1084.81,443.8 -2740.32,443.8 -2740.32,-1307.53 -2740.32,-1468.98
no net on Top Layer "3.3V Input Top" (solid, shelved, pour order 0): -2740.32,443.8

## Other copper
Top Layer:
  rectangle net 3V3: -735.58,1318 -713.58,1695.27
  rectangle net +5: -705.58,498 -680.58,1700.72
  region net GND: -830.46,-3317.98 -800.95,-3314.36 -1039.93,-1367.97 -1069.44,-1371.6
  region net 3V3: -493.25,-3313.86 -471.46,-3311.18 -618.38,-2114.6 -640.17,-2117.27
  region net +5: -462.46,-3308.35 -438.19,-3305.37 -584.9,-2110.46 -609.17,-2113.44
  rectangle net +5: -463.46,-3780.18 -438.46,-3301.18
  rectangle net 3V3: -493.46,-3778.18 -471.46,-3309.99
  pour cut-out: -1610.17,332.5 -1610.17,131.72 -1409.38,131.72 -1409.39,131.72 -1409.39,332.5
  pour cut-out: -1829,231.11 -1906,231.11 -1906,25 -1543,25 -1543,140 -1738.51,140 -1772,173.49 -1772,231.11 -1828.38,231.11 -1829,230.49
  region net SPR_GPO1: -878,-1391
  pour cut-out: -1084.81,1901.16 -671.43,1901.16 -671.43,1790.49 -1084.81,1790.49
  pour cut-out: 30,30 -2392.21,30 -2392.21,-1211.1 30,-1211.1
  pour cut-out: -842.69,-3790.18 -429.3,-3790.18 -429.3,-3957.5 -842.69,-3957.5
Bottom Layer:
  rectangle net +5: -732.46,425 -615,481
  rectangle net 3V3: -734.46,1345.82 -713.58,1695.27
  rectangle net 3V3: -814.46,1257.82 -713.46,1317.82
  rectangle net 3V3: -734.46,1257.82 -713.46,1373.82
  rectangle net 3V3: -814.46,363.11 -752.46,1317.82
  rectangle net +5: -732.46,425 -680.58,1244.82
  rectangle net +5: -705.58,425 -680.58,1700.72
  region net 3V3: -493.25,-3313.86 -471.46,-3311.18 -697.25,-1472.26 -719.04,-1474.93
  region net +5: -462.46,-3308.36 -438.19,-3305.38 -659.92,-1499.52 -684.19,-1502.5
  rectangle net +5: -463.46,-3780.18 -438.46,-3301.18
  rectangle net 3V3: -493.46,-3778.18 -471.46,-3309.99
  pour cut-out: -1084.81,1901.16 -671.43,1901.16 -671.43,1790.49 -1084.81,1790.49
  pour cut-out: -2392.21,-1211.1 30,-1211.1 30,30 -2392.21,30
  pour cut-out: -2492.87,-1314.55
  pour cut-out: -842.69,-3957.5 -842.69,-3790.18 -429.3,-3790.18 -429.3,-3957.5

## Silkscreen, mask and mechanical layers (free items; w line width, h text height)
Bottom Overlay:
  circle w12: c-1065.13,1773.17 r4
  circle w20: c-1190.69,-601.5 r10.82
  circle w12: c-823.49,-3778.18 r4
  lines w20: -1387.48,-316.89 ccw(c-1190.69,-601.5) -1373.11,-895.53 ; -1359.49,-364.65 ccw(c-1190.69,-601.5) -1347.28,-846.6 ; -1333.5,-414.59 ccw(c-1190.69,-601.5) -1320.72,-797.52 ; -1299.7,-462.29 ccw(c-1190.69,-601.5) -1293.1,-745.64 ; -1271.84,-504.14 ccw(c-1190.69,-601.5) -1266.55,-703.05 ; -1239,-660.24 cw(c-1190.69,-601.5) -1238.68,-542.51 ; -1142.69,-542.51 cw(c-1190.69,-601.5) -1142.37,-660.24 ; -1114.82,-703.05 ccw(c-1190.69,-601.5) -1109.53,-504.14 ; -1088.27,-745.64 ccw(c-1190.69,-601.5) -1081.67,-462.29 ; -1060.65,-797.52 ccw(c-1190.69,-601.5) -1047.87,-414.59 ; -1034.09,-846.6 ccw(c-1190.69,-601.5) -1021.88,-364.65 ; -1008.26,-895.53 ccw(c-1190.69,-601.5) -993.9,-316.89
  text "J2" at -1068,1732 h28
  text "J1" at -783.63,-3762.49 h28
Mechanical 1:
  drawing of 4193 lines, arcs and shapes, not listed
  text "6" at -9100.44,4978.17 h121.11
  text "5" at -5557.13,4978.17 h121.11
  text "4" at -2013.82,4978.17 h121.11
  text "3" at 1529.48,4978.17 h121.11
  text "2" at 5072.79,4978.17 h121.11
  text "1" at 8616.1,4978.17 h121.11
  text "APPD/DATE" at 10118.92,4643.08 h80.74
  text "ZONE" at 4660.7,4640.5 h80.74
  text "ECN" at 3772.54,4637.47 h80.74
  text "ISSUE" at 4216.62,4637.47 h80.74
  text "DESCRIPTION" at 6694.78,4637.47 h80.74
  text "DRN/DATE" at 8901.93,4637.47 h80.74
  text "CHK/DATE" at 9514.8,4637.47 h80.74
  text "NOTE: THIS DRAWING WAS PRODUCED BY COMPUTER, DO NOT UPDATE MANUALLY" at -10673.66,4488.49 h157.48
  text "E" at -11006.76,3300.75 h121.11
  text "E" at 10598.87,3300.75 h121.11
  text "9,35" at 4001.3,1764.51 h137.8
  text "R0,4" at -5699.14,1446.66 h137.8 r322.13
  text "R0,4" at -5469.64,1421.25 h137.8 r28.27
  text "R0,4" at -5929.75,1261.28 h137.8 r49.62
  text "1,9" at 5286.8,1076.05 h137.8 r90
  text "18,3" at 5895.82,916.38 h137.8 r90
  text "R0,4" at -5219.05,696.83 h137.8 r346.55
  text "Top Ben End" at -1359.78,651.47 h19.68
  text "Top Ben Start" at -1395.78,554.47 h19.68
  text "R1,5" at -5304.58,400.15 h137.8 r297.71
  text "5,7" at 4044.26,370.67 h137.8
  text "D" at -11006.76,308.63 h121.11
  text "D" at 10598.87,308.63 h121.11
  text "10,6" at -293.39,150.83 h137.8
  text "42,2" at 5894.95,-274.5 h137.8 r90
  text "3,2" at 4418.46,-730.13 h137.8
  text "R1,5" at -5547.85,-766.61 h137.8 r52.37
  text "Old Bend Start" at -2186.78,-952.53 h19.68
  text "R1,7" at -5452.38,-953.42 h137.8 r19.46
  text "Back Metal Plate Start" at -2342.78,-1210.53 h19.68
  text "Spring Start" at -2345.78,-1444.53 h19.68
  text "56" at 5887.2,-2207.57 h137.8 r90
  text "C" at -11018.3,-2683.5 h121.11
  text "C" at 10598.87,-2683.5 h121.11
  text "~}" at -1493.14,-2735.46 h137.8
  text "R1,7" at -5329.43,-3156.58 h137.8 r337.84
  text "R1,7" at -5548.78,-3163.7 h137.8 r324.73
  text "3,2" at 4180.6,-3287.6 h137.8
  text "R0,4" at -5468.72,-3428.23 h137.8 r323.84
  text "2" at 4266.36,-3860.94 h137.8
  text "6" at 5885.12,-3866.33 h137.8 r90
  text "B" at -11006.76,-5675.62 h121.11
  text "B" at 10598.87,-5675.62 h121.11
  text "Coremi Industries Co., Limited" at 5924.31,-8494.95 h196.85
  text "T10" at 9854.37,-8643.27 h137.8
  text "A" at -11041.37,-8667.75 h121.11
  text "A" at 10598.87,-8667.75 h121.11
  text "REVISION NO." at 8869.71,-8682.02 h99.5
  text "DRAWING NO." at 5922.31,-8748.95 h99.5
  text "Airzai-041T10" at 7166.31,-8771.95 h137.8
  text "Airzai" at 9044.4,-8834.07 h137.8
  text "MODEL :" at 8397.27,-8918.24 h99.5
  text "MANIFOLD_SOLID_BREP_27740" at 6472.31,-8961.95 h98.43
  text "TITLE:" at 5908.31,-8963.95 h99.5
  text "METERIAL:" at 5916.96,-9154.46 h99.5
  text "MASS :                 kg" at 8397.27,-9154.46 h99.5
  text "1" at 7671.08,-9353.06 h137.8
  text "P/N:" at 8397.27,-9381.37 h118.11
  text "FINISH:" at 5916.96,-9390.68 h99.5
  text "QTY:" at 7196.49,-9390.68 h99.5
  text "NOTE:" at -10131.12,-9474.19 h118.11
  text ".  TOLERANCES  ." at 7165.66,-9555.14 h79.6
  text "1:1" at 6448.99,-9580.77 h137.8
  text "1.UNSPECIFIED DRAFT ANGLE 1.0\Fgdt;{\Fgdt;~}" at -10131.12,-9593.49 h118.11
  text "SCALE:" at 5916.96,-9626.9 h99.5
  text "DRN.DATE" at 8397.27,-9626.9 h99.5
  text "Daniel Apr/20,2019" at 9050.72,-9650.83 h118.11
  text "All dimensions are in mm" at 7159.29,-9686.2 h59.7
  text "\Ftxt;2.UNSPECIFIED FILLET TO BE R0.3" at -10131.12,-9712.78 h118.11
  text "Daniel Apr/20,201" at 9050.72,-9770.13 h118.11
  text "unless otherwise specified." at 7168.85,-9794.56 h59.7
  text "A2" at -10759.76,-9858.38 h236.22
  text "PROJECTION" at 5916.96,-9863.12 h99.5
  text "CHK.DATE" at 8397.27,-9863.12 h99.5
  text "X" at 7461.09,-9890.91 h59.7
  text "0.20" at 7868.2,-9890.91 h59.7
  text ".X" at 7461.09,-9977.73 h59.7
  text "0.10" at 7868.2,-9977.73 h59.7
  text ".XX" at 7461.09,-10064.54 h59.7
  text "0.05" at 7868.2,-10064.54 h59.7
  text "1  1" at 6434.84,-10088.83 h137.8
  text "SHEET   OF" at 5916.96,-10099.34 h99.5
  text "APP.DATE" at 8397.27,-10099.34 h99.5
  text "ANGLE" at 7445.76,-10151.35 h59.7
  text "~}" at 7868.2,-10151.35 h59.7
  text "6" at -9100.44,-10375.2 h121.11
  text "5" at -5557.13,-10375.2 h121.11
  text "4" at -2013.82,-10375.2 h121.11
  text "3" at 1529.48,-10375.2 h121.11
  text "2" at 5072.79,-10375.2 h121.11
  text "1" at 8616.1,-10375.2 h121.11
Mechanical 2:
  rectangle: -1084.81,1760.3 -671.43,1901.16
  rectangle: -842.69,-3957.5 -429.3,-3780.98
  lines w0.5: 6706.31,-9889.06 6889.04,-9889.06 ; 6797.67,-9980.43 6797.67,-9797.69 ; 6848.22,-9889.71 7136.02,-9889.71
  lines w8: -2992.69,-967.5 -2592.69,-967.5 ccw(c-2592.69,-846.79) -2507.33,-932.15 -903.63,671.55 ccw(c-988.99,756.91) -868.28,756.91 -868.28,1692.5 ; -2642.69,-967.5 -2562.69,-967.5 cw(c-2562.69,-1088.21) -2477.33,-1002.86 -678.04,-2802.15 cw(c-763.4,-2887.5) -642.69,-2887.5 -642.69,-3767.5 ; -868.28,1692.5 -852.87,1677.09 cw(c-877.47,1652.5) -842.69,1652.5 -892.69,1652.5 cw(c-855.05,1652.5) -881.66,1679.11 -868.28,1692.5 ; -642.69,-3767.5 -629.3,-3754.12 ccw(c-655.91,-3727.5) -618.28,-3727.5 -668.28,-3727.5 ccw(c-633.49,-3727.5) -658.09,-3752.1 -642.69,-3767.5
  text "Stiffener Location" at -3542.69,-982.18 h30
Mechanical 4:
  the board outline again, w0.51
